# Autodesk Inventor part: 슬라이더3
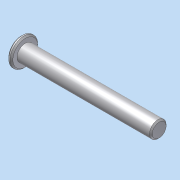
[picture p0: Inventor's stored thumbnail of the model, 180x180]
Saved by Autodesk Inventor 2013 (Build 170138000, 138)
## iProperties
Company: 한국ATC센터
Created: 2015-04
Part Number: 슬라이더3
Document SubType Name: Modeling
Designer: KYOUNG IL JANG
Density: 1 g/cm^3
Material: 일반
Mass: 11.8344 g
Surface Area: 43.7403 cm^2
Volume: 11.8344 cm^3
Author: KYOUNG IL JANG
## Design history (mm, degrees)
sketch "스케치1"
  geometry: L1 (0, 0)-(0, 10); L2 (0, 10)-(-3, 10); L3 (-3, 10)-(-3, 6); L4 (-3, 6)-(-100, 6); L5 (-100, 6)-(-100, 0); L6 (-100, 0)-(0, 0)
  constraints: 12 end point, 4 parallel, 1 perpendicular, 1 vertical
  dimensions: "d0" = 12 diameter of L4 L6; "d1" = 20 diameter of L2 L6; "d2" = 3 distance between parallel lines of L3 L1; "d3" = 100 distance between parallel lines of L5 L1
revolve "회전1" sketch "스케치1" stored, may be unused: angle "d4" = 90 deg
chamfer "모따기1" distance "d5" = 1; stored, may be unused: second distance "d6" = 2, angle "d7" = 45 deg
node "솔리드1"
